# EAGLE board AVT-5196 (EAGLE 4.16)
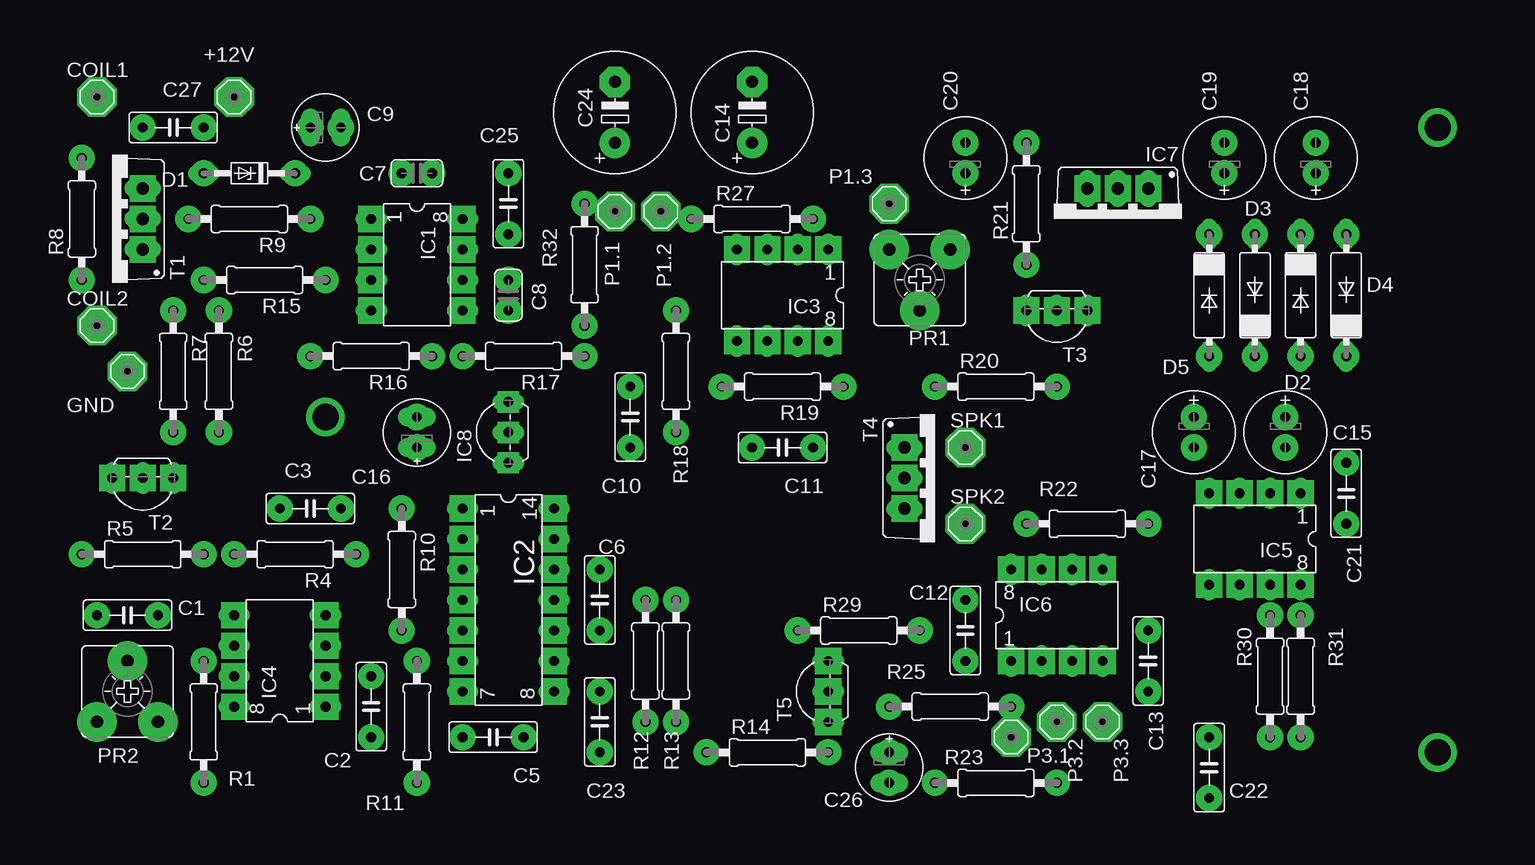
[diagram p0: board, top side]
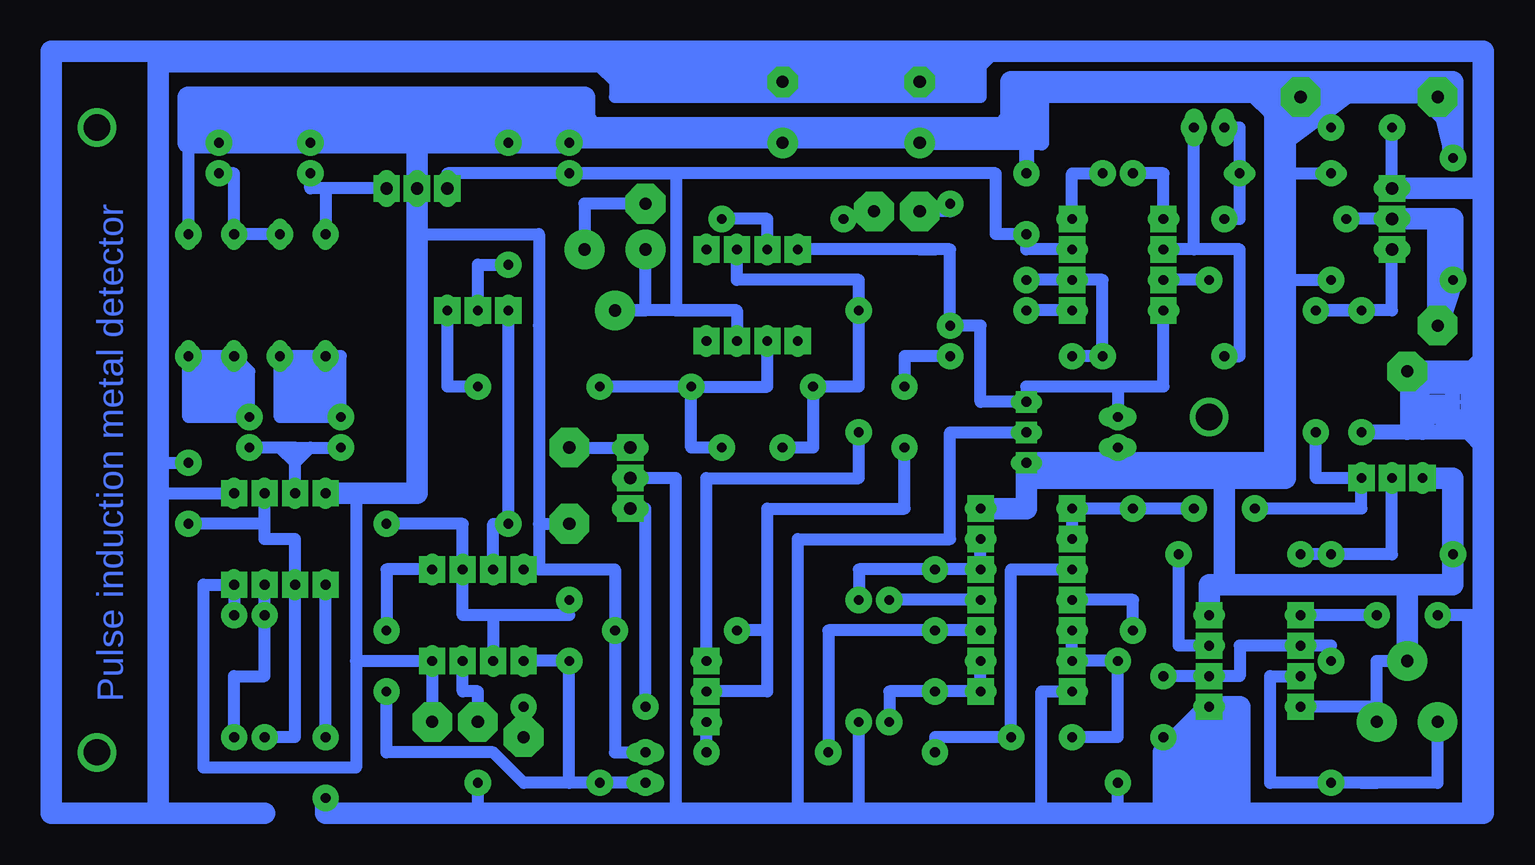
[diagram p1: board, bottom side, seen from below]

No outline drawn. Coordinates in mm, seen from the top.
Copper layers 16: Bottom 0.035mm
Design rules "default": minimum track width 10mil, minimum drill 24mil, track to track 8mil, track to pad 8mil, pad to pad 8mil, via to via 8mil, smd to smd 8mil, copper to edge 40mil, drill to drill 8mil, minimum pad ring 10mil, minimum via ring 8mil, stop-mask expansion 0mil, vias tented up to drill 0mil, thermal gap 10mil

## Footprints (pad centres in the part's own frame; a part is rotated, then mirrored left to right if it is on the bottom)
MCS10B = drill 1.016 pad 2.159 octagon: MP 0,0
C050-025X075 = drill 0.813 octagon: 1 -2.54,0; 2 2.54,0
C025-024X044 = drill 0.813 octagon: 1 -1.27,0; 2 1.27,0
E2,5-6E = drill 0.813 pad 1.575 long: + -1.27,0; - 1.27,0
E5-10,5 = drill 1.016 pad 2.54 round: + -2.54,0 | drill 1.016 pad 2.54 octagon: - 2.54,0
E2,5-7 = drill 0.813 pad 1.6 round: + -1.27,0 | drill 0.813 pad 1.6 octagon: - 1.27,0
DO34Z7 = drill 0.813 long: A 3.81,0; K -3.81,0
DO07 = drill 0.813 long: A 5.08,0; K -5.08,0
DIL08 = drill 0.813 long: 1 -3.81,-3.81; 2 -1.27,-3.81; 3 1.27,-3.81; 4 3.81,-3.81; 5 3.81,3.81; 6 1.27,3.81; 7 -1.27,3.81; 8 -3.81,3.81
DIL14 = drill 0.813 long: 1 -7.62,-3.81; 2 -5.08,-3.81; 3 -2.54,-3.81; 4 0,-3.81; 5 2.54,-3.81; 6 5.08,-3.81; 7 7.62,-3.81; 8 7.62,3.81; 9 5.08,3.81; 10 2.54,3.81; 11 0,3.81; 12 -2.54,3.81; 13 -5.08,3.81; 14 -7.62,3.81
TO220V = drill 1.016 long: 1 -2.54,-2.54; 2 0,-2.54; 3 2.54,-2.54
TO92- = drill 0.813 long: 1 2.54,-1.27; 2 0,-1.27; 3 -2.54,-1.27
CA6V = drill 1.016 long: 1 -2.54,-2.54; 2 0,2.54; 3 2.54,-2.54
0207/10 = drill 0.813 octagon: 1 -5.08,0; 2 5.08,0

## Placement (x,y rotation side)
+12V  [MCS10B]  2.54,80.01 0 top
C1  [C050-025X075]  -6.35,36.83 0 top
C2  [C050-025X075]  13.97,29.21 90 top
C3  [C050-025X075]  8.89,45.72 0 top
C5  [C050-025X075]  24.13,26.67 0 top
C6  [C050-025X075]  33.02,38.1 90 top
C7  [C025-024X044]  17.78,73.66 180 top
C8  [C025-024X044]  25.4,63.5 90 top
C9  [E2,5-6E]  10.16,77.47 0 top
C10  [C050-025X075]  35.56,53.34 90 top
C11  [C050-025X075]  48.26,50.8 180 top
C12  [C050-025X075]  63.5,35.56 270 top
C13  [C050-025X075]  78.74,33.02 270 top
C14  [E5-10,5]  45.72,78.74 90 top
C15  [E2,5-7]  90.17,52.07 270 top
C16  [E2,5-6E]  17.78,52.07 90 top
C17  [E2,5-7]  82.55,52.07 270 top
C18  [E2,5-7]  92.71,74.93 90 top
C19  [E2,5-7]  85.09,74.93 90 top
C20  [E2,5-7]  63.5,74.93 90 top
C21  [C050-025X075]  95.25,46.99 270 top
C22  [C050-025X075]  83.82,24.13 270 top
C23  [C050-025X075]  33.02,27.94 90 top
C24  [E5-10,5]  34.29,78.74 90 top
C25  [C050-025X075]  25.4,71.12 90 top
C26  [E2,5-6E]  57.15,24.13 270 top
C27  [C050-025X075]  -2.54,77.47 0 top
COIL1  [MCS10B]  -8.89,80.01 0 top
COIL2  [MCS10B]  -8.89,60.96 0 top
D1  [DO34Z7]  3.81,73.66 180 top
D2  [DO07]  91.44,63.5 270 top
D3  [DO07]  87.63,63.5 90 top
D4  [DO07]  95.25,63.5 90 top
D5  [DO07]  83.82,63.5 270 top
GND  [MCS10B]  -6.35,57.15 0 top
IC1  [DIL08]  17.78,66.04 270 top
IC2  [DIL14]  25.4,38.1 270 top
IC3  [DIL08]  48.26,63.5 180 top
IC4  [DIL08]  6.35,33.02 90 top
IC5  [DIL08]  87.63,43.18 180 top
IC6  [DIL08]  71.12,36.83 0 top
IC7  [TO220V]  76.2,69.85 180 top
IC8  [TO92-]  24.13,52.07 90 top
P1.1  [MCS10B]  34.29,70.48 0 top
P1.2  [MCS10B]  38.1,70.48 0 top
P1.3  [MCS10B]  57.15,71.12 0 top
P3.1  [MCS10B]  67.31,26.67 0 top
P3.2  [MCS10B]  71.12,27.94 0 top
P3.3  [MCS10B]  74.93,27.94 0 top
PR1  [CA6V]  59.69,64.77 180 top
PR2  [CA6V]  -6.35,30.48 0 top
R1  [0207/10]  0,27.94 90 top
R4  [0207/10]  7.62,41.91 180 top
R5  [0207/10]  -5.08,41.91 0 top
R6  [0207/10]  1.27,57.15 270 top
R7  [0207/10]  -2.54,57.15 270 top
R8  [0207/10]  -10.16,69.85 90 top
R9  [0207/10]  3.81,69.85 180 top
R10  [0207/10]  16.51,40.64 270 top
R11  [0207/10]  17.78,27.94 270 top
R12  [0207/10]  36.83,33.02 270 top
R13  [0207/10]  39.37,33.02 270 top
R14  [0207/10]  46.99,25.4 0 top
R15  [0207/10]  5.08,64.77 180 top
R16  [0207/10]  13.97,58.42 180 top
R17  [0207/10]  26.67,58.42 180 top
R18  [0207/10]  39.37,57.15 90 top
R19  [0207/10]  48.26,55.88 180 top
R20  [0207/10]  66.04,55.88 0 top
R21  [0207/10]  68.58,71.12 90 top
R22  [0207/10]  73.66,44.45 180 top
R23  [0207/10]  66.04,22.86 0 top
R25  [0207/10]  62.23,29.21 180 top
R27  [0207/10]  45.72,69.85 0 top
R29  [0207/10]  54.61,35.56 0 top
R30  [0207/10]  88.9,31.75 90 top
R31  [0207/10]  91.44,31.75 90 top
R32  [0207/10]  31.75,66.04 270 top
SPK1  [MCS10B]  63.5,50.8 0 top
SPK2  [MCS10B]  63.5,44.45 0 top
T1  [TO220V]  -7.62,69.85 90 top
T2  [TO92-]  -5.08,46.99 180 top
T3  [TO92-]  71.12,60.96 180 top
T4  [TO220V]  60.96,48.26 270 top
T5  [TO92-]  50.8,30.48 90 top

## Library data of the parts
+12V COIL1 COIL2 GND P1.1-P1.3 P3.1-P3.3 SPK1 SPK2 = solpad
C1-C3 C5-C27 R1 R4-R23 R25 R27 R29-R32 = rcl
D1-D5 = diode
IC1 IC3-IC6 = dil
IC2 = 40xx
IC7 IC8 T1-T5 = transistor-npn
PR1 PR2 = pot

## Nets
S$1: COIL2.MP R8.1 R9.2 T1.2
S$2: R6.1 R7.1 T1.1
S$3: C19.+ D5.K IC7.1
S$4: C10.2 R17.1
S$5: C3.1 R6.2 T2.3
S$6: R4.2 R5.2 T2.2
S$8: C3.2 IC2.1 IC2.2
S$9: IC4.3 R4.1
S$10: C16.+ C18.- C19.- C20.- C25.2 C26.+ COIL1.MP D1.A D4.A IC2.14 IC4.4 IC4.8 IC5.4 IC5.8 IC6.4 IC6.8 IC7.2 IC8.3 P3.3.MP PR2.2 PR2.3 R5.1 R8.2 R15.2 R21.2 R29.2 R31.2 SPK2.MP T2.1
S$11: C2.2 IC4.2 IC4.6 R1.2
S$12: C1.2 IC4.5
S$13: IC2.4 R10.2
S$14: C5.1 IC2.5 IC2.6 R11.1
S$15: C5.2 C23.1 IC2.3
S$16: C23.2 IC2.8 IC2.9 R12.2
S$17: C6.1 IC2.10 R14.1
S$18: C12.2 C13.2 C26.- IC6.1 R23.1
S$19: IC2.11 R12.1
S$20: C6.2 IC2.12 IC2.13 R13.1
S$21: C11.1 IC3.6 R19.1 R20.1
S$22: C9.+ D1.K R9.1
S$23: C7.2 IC1.1
S$24: C7.1 IC1.8
S$25: R18.1 T5.1
S$26: C8.1 IC1.5
S$27: C22.1 IC5.5
S$28: C9.- IC1.2 R16.2
S$29: IC1.3 R15.1
S$30: IC6.7 R22.2 T3.1
S$31: C8.2 IC1.6 R16.1 R17.2
S$32: C10.1 R29.1 T5.2
S$33: R14.2 T5.3
S$34: C1.1 C2.1 C14.- C21.1 C22.2 C24.- GND.MP IC2.7 IC4.1 IC5.1 IC8.2 R7.2 R11.2 R13.2 R23.2 T1.3 T4.2
S$35: C16.- IC1.4 IC3.4 IC8.1 R32.2
S$36: IC3.3 R27.2
S$37: C11.2 IC3.2 R18.2 R19.2
S$38: P3.1.MP R25.1
S$39: P1.1.MP R32.1
S$40: P1.2.MP R27.1
S$41: P1.3.MP PR1.1
S$42: R20.2 T3.3
S$43: R21.1 T3.2
S$44: C12.1 IC6.2 IC6.6 R22.1
S$47: C21.2 IC5.2 IC5.6 R30.1
S$48: IC5.7 R30.2 R31.1
S$49: C15.- C17.- IC5.3
S$50: C17.+ D3.K D5.A
S$51: C15.+ D2.A D4.K
S$52: D2.K D3.A
S$53: IC4.7 PR2.1 R1.1
S$54: C13.1 IC6.5
S$55: C20.+ C25.1 IC1.7 IC3.7 IC7.3 PR1.2 PR1.3

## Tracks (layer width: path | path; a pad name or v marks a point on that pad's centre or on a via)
S$1  (via drill 0.25 pad 3.3)
  Bottom 1.016: T1.2 R9.2 | COIL2.MP R8.1
  Bottom 1.778: -8.89,69.85 -10.16,69.85 R8.1 COIL2.MP -8.89,69.85 | -8.89,69.85 T1.2
  other vias: -8.89,60.96
S$2
  Bottom 1.016: R7.1 R6.1 -5.08,62.23 T1.1
S$3
  Bottom 1.016: 83.82,72.39 D5.K | IC7.1 83.82,72.39 | 83.82,72.39 85.09,72.39 C19.+
S$4
  Bottom 1.016: R17.1 35.56,58.42 C10.2
S$5
  Bottom 1.016: C3.1 -2.54,45.72 T2.3 1.27,48.26 R6.2
S$6
  Bottom 1.016: T2.2 -5.08,41.91 R5.2 R4.2
S$7  (via drill 0.25 pad 2.18)
  other vias: 78.74,72.39
S$8
  Bottom 1.016: IC2.2 IC2.1 C3.2
S$9
  Bottom 1.016: IC4.3 12.7,34.29 R4.1
S$10  (via drill 0.25 pad 2.18, 0.25 pad 3.3)
  Bottom 1.016: C26.+ 59.69,25.4 R29.2 59.69,40.64 66.04,40.64 | R31.2 IC5.8 93.98,39.37 93.98,24.13 81.28,24.13 | 66.04,40.64 IC6.8 | 66.04,44.45 SPK2.MP | 66.04,44.45 66.04,40.64 | P3.3.MP IC6.4 81.28,33.02 | 81.28,33.02 81.28,24.13 | 66.04,68.58 66.04,60.96 | 66.04,68.58 66.04,44.45 | 95.25,80.01 92.71,80.01 | 85.09,80.01 C19.- | 85.09,80.01 92.71,80.01 | C18.- 92.71,80.01 | 95.25,76.2 D4.A | 76.2,68.58 66.04,68.58 | 81.28,46.99 81.28,33.02 | 81.28,46.99 81.28,24.13 | 81.28,46.99 IC5.4 | 68.58,80.01 R21.2 | 68.58,80.01 63.5,80.01 63.5,78.74 | 81.28,46.99 76.2,46.99 76.2,68.58 | 76.2,68.58 IC7.2 76.2,76.2 76.2,80.01 | 76.2,80.01 85.09,80.01 | 76.2,80.01 68.58,80.01 | 60.96,77.47 62.23,78.74 | 27.94,77.47 26.67,78.74 | C25.2 25.4,76.2 | 25.4,76.2 25.4,77.47 25.4,80.01 | 25.4,76.2 34.29,76.2 C20.- | R8.2 COIL1.MP -1.27,80.01 0,80.01 2.54,80.01 3.81,80.01 5.08,80.01 | 24.13,80.01 6.35,80.01 5.08,80.01 | 5.08,80.01 5.08,78.74 5.08,73.66 | 5.08,73.66 D1.A | 5.08,64.77 5.08,73.66 | 5.08,64.77 R15.2 | 5.08,64.77 5.08,49.53 8.89,49.53 | -6.35,39.37 8.89,39.37 | PR2.2 -3.81,33.02 -3.81,29.21 | -3.81,29.21 IC4.8 | PR2.3 -3.81,29.21 | 17.78,49.53 C16.+
  Bottom 1.27: 24.13,81.28 25.4,81.28 25.4,80.01 | 34.29,76.2 24.13,76.2 24.13,80.01 25.4,80.01 | 25.4,80.01 C25.2 | -10.16,77.47 COIL1.MP R8.2 -10.16,77.47 | -10.16,77.47 -6.35,81.28 -10.16,81.28 -10.16,77.47 | 5.08,78.74 6.35,80.01 | 3.81,76.2 -1.27,80.01 | 2.54,80.01 2.54,78.74 0,80.01 3.81,77.47 2.54,80.01
  Bottom 1.778: 93.98,77.47 64.77,77.47 | 93.98,77.47 93.98,78.74 63.5,78.74 C20.- 76.2,76.2 | IC5.4 76.2,46.99 76.2,76.2 | 93.98,76.2 95.25,76.2 95.25,80.01 62.23,80.01 62.23,78.74 62.23,77.47 60.96,77.47 27.94,77.47 25.4,77.47 | 93.98,76.2 C18.- | 93.98,76.2 93.98,77.47 | 76.2,76.2 93.98,76.2 | 26.67,78.74 26.67,81.28 24.13,81.28 -2.54,81.28 | -2.54,81.28 -6.35,81.28 COIL1.MP | 3.81,80.01 3.81,77.47 3.81,76.2 3.81,53.34 | IC2.14 25.4,45.72 25.4,48.26 | 3.81,53.34 3.81,48.26 25.4,48.26 | T2.1 -10.16,48.26 R5.1 -10.16,39.37 -6.35,39.37 | 25.4,48.26 IC8.3 17.78,49.53 8.89,49.53 | 3.81,53.34 3.81,49.53 8.89,49.53 | 10.16,39.37 IC4.4 | 8.89,49.53 8.89,39.37 10.16,39.37 | -6.35,39.37 10.16,39.37 | PR2.2 -6.35,39.37 | -2.54,81.28 -10.16,81.28 R8.2
  other vias: -8.89,80.01 63.5,44.45 -10.16,74.93
S$11
  Bottom 1.016: R1.2 0,34.29 IC4.6 7.62,34.29 7.62,31.75 IC4.2 C2.2
S$12
  Bottom 1.016: C1.2 IC4.5
S$13
  Bottom 1.016: R10.2 16.51,38.1 IC2.4
S$14
  Bottom 1.016: C5.1 17.78,26.67 R11.1 IC2.6 IC2.5
S$15
  Bottom 1.016: IC2.3 26.67,40.64 C5.2 33.02,26.67 C23.1
S$16
  Bottom 1.016: IC2.9 IC2.8 C23.2 36.83,30.48 R12.2
S$17
  Bottom 1.016: IC2.10 C6.1 41.91,35.56 R14.1
S$18
  Bottom 1.016: IC6.1 C12.2 63.5,22.86 | 63.5,22.86 R23.1 C26.- | C13.2 78.74,25.4 69.85,25.4 67.31,22.86 63.5,22.86
S$19
  Bottom 1.016: IC2.11 R12.1
S$20
  Bottom 1.016: IC2.12 C6.2 39.37,40.64 | IC2.12 IC2.13 IC2.12 | 39.37,40.64 R13.1 | IC2.12 39.37,40.64
S$21
  Bottom 1.016: IC3.6 46.99,55.88 R19.1 | R19.1 53.34,50.8 C11.1 | R19.1 R20.1
S$22
  Bottom 1.016: R9.1 7.62,69.85 D1.K 7.62,77.47 C9.+
S$23
  Bottom 1.016: IC1.1 13.97,73.66 C7.2
S$24
  Bottom 1.016: IC1.8 21.59,73.66 C7.1
S$25
  Bottom 1.016: R18.1 39.37,48.26 52.07,48.26 T5.1
S$26
  Bottom 1.016: IC1.5 C8.1
S$27
  Bottom 1.016: C22.1 IC5.5
S$28
  Bottom 1.016: 11.43,67.31 7.62,67.31 7.62,58.42 R16.2 | 11.43,67.31 C9.- | 11.43,67.31 IC1.2
S$29
  Bottom 1.016: R15.1 IC1.3
S$30
  Bottom 1.016: T3.1 R22.2 69.85,44.45 IC6.7
S$31
  Bottom 1.016: C8.2 IC1.6 19.05,64.77 R16.1 R17.2
S$32
  Bottom 1.016: C10.1 35.56,45.72 46.99,45.72 46.99,35.56 | 46.99,35.56 R29.1 | 46.99,35.56 46.99,30.48 T5.2
S$33
  Bottom 1.016: R14.2 T5.3
S$34  (via drill 0.25 pad 2.18)
  Bottom 1.016: 97.79,46.99 IC5.1 | 97.79,49.53 C21.1 | 97.79,49.53 97.79,46.99 | IC8.2 31.75,52.07 31.75,43.18 44.45,43.18 44.45,20.32 | 97.79,38.1 97.79,46.99 | 97.79,49.53 97.79,82.55 60.96,82.55 | 46.99,83.82 45.72,83.82 | 45.72,83.82 C14.- | T4.2 54.61,48.26 54.61,20.32 | 71.12,20.32 R23.2 | 71.12,20.32 83.82,20.32 | 54.61,20.32 71.12,20.32 | 44.45,20.32 54.61,20.32 | 34.29,83.82 45.72,83.82 | 34.29,83.82 34.29,82.55 | 34.29,83.82 C24.- | 34.29,83.82 27.94,83.82 29.21,82.55 | T1.3 -5.08,77.47 | IC2.7 24.13,30.48 24.13,20.32 | 39.37,20.32 44.45,20.32 | 39.37,20.32 54.61,20.32 | 39.37,20.32 R13.2 | IC4.1 10.16,26.67 12.7,26.67 C2.1 13.97,25.4 | 24.13,20.32 39.37,20.32 | -6.35,52.07 R7.2 | 17.78,20.32 24.13,20.32 | 17.78,20.32 R11.2 | 13.97,20.32 17.78,20.32 | -12.7,36.83 -12.7,50.8 | -12.7,36.83 -11.43,36.83 | -11.43,36.83 C1.1 | -12.7,20.32 -12.7,36.83 | -11.43,20.32 -11.43,36.83 | 29.21,82.55 29.21,81.28 | 29.21,81.28 29.21,80.01 59.69,80.01 59.69,81.28 | 59.69,83.82 59.69,82.55 | 29.21,82.55 30.48,82.55 | 29.21,82.55 30.48,81.28 | 30.48,81.28 31.75,81.28 | 31.75,81.28 39.37,81.28 | 41.91,81.28 39.37,81.28 | 58.42,81.28 41.91,81.28 | 59.69,82.55 58.42,82.55 | 58.42,82.55 53.34,82.55 | 33.02,82.55 38.1,82.55 | 31.75,82.55 33.02,82.55 | 30.48,82.55 31.75,82.55 | 30.48,82.55 30.48,81.28 | 30.48,81.28 31.75,82.55 | 31.75,81.28 31.75,82.55 | 31.75,81.28 33.02,82.55 | 33.02,82.55 39.37,81.28 | 58.42,82.55 39.37,81.28 | 58.42,81.28 53.34,82.55 | 53.34,82.55 38.1,82.55 | 41.91,81.28 38.1,82.55 | 58.42,82.55 41.91,81.28 | 58.42,81.28 58.42,82.55 | 59.69,82.55 59.69,81.28 | 58.42,81.28 59.69,82.55 | 58.42,81.28 59.69,81.28 | 29.21,81.28 58.42,81.28 | 59.69,82.55 60.96,82.55 | 59.69,81.28 60.96,82.55
  Bottom 1.27: GND.MP -6.35,52.07 -7.62,52.07 | -12.7,52.07 -11.43,52.07 | -11.43,52.07 -7.62,52.07 | -7.62,52.07 R7.2 | -7.62,52.07 -7.62,54.61 | -7.62,54.61 -7.62,55.88 -10.16,55.88 | -10.16,55.88 -11.43,55.88 -11.43,53.34 | -11.43,53.34 -10.16,53.34 | -10.16,53.34 -8.89,53.34 -7.62,54.61 | -7.62,54.61 -8.89,54.61 | -8.89,54.61 -10.16,54.61 | -10.16,53.34 -10.16,55.88 | -7.62,52.07 -8.89,54.61 | -11.43,53.34 -12.7,50.8 -11.43,52.07 | -11.43,53.34 -11.43,52.07 | -12.7,58.42 -10.16,55.88
  Bottom 1.778: -12.7,57.15 GND.MP | -12.7,57.15 -12.7,58.42 -12.7,72.39 | -12.7,72.39 -12.7,83.82 27.94,83.82 50.8,83.82 | -12.7,72.39 T1.3 | 50.8,83.82 59.69,83.82 97.79,83.82 | 50.8,83.82 46.99,83.82 | 97.79,83.82 97.79,82.55 97.79,38.1 97.79,20.32 | 97.79,20.32 96.52,20.32 | 7.62,20.32 13.97,20.32 | 7.62,20.32 -11.43,20.32 -12.7,20.32 -12.7,50.8 -12.7,52.07 -12.7,57.15 | IC4.1 7.62,29.21 7.62,20.32 | 7.62,20.32 11.43,20.32 12.7,21.59 12.7,25.4 8.89,25.4 | 8.89,25.4 8.89,27.94 | 8.89,25.4 8.89,21.59 11.43,21.59 11.43,24.13 10.16,24.13 | 10.16,24.13 10.16,22.86 | IC4.1 10.16,24.13 | IC4.1 12.7,26.67 13.97,25.4 13.97,20.32 | 97.79,20.32 106.68,20.32 106.68,83.82 97.79,83.82 | 97.79,20.32 88.9,20.32 | C22.2 83.82,20.32 13.97,20.32
  other vias: 83.82,21.59
S$35
  Bottom 1.016: 17.78,55.88 C16.- | 17.78,55.88 25.4,55.88 IC8.1 29.21,54.61 29.21,60.96 R32.2 31.75,67.31 34.29,67.31 | IC1.4 13.97,55.88 17.78,55.88 | 34.29,67.31 33.02,67.31 | 34.29,67.31 IC3.4
S$36
  Bottom 1.016: IC3.3 46.99,69.85 R27.2
S$37
  Bottom 1.016: C11.2 43.18,50.8 R19.2 39.37,55.88 R18.2 39.37,64.77 49.53,64.77 IC3.2
S$38
  Bottom 1.016: P3.1.MP R25.1
S$39
  Bottom 1.016: R32.1 31.75,70.48 P1.1.MP
S$40
  Bottom 1.016: P1.2.MP R27.1
S$41
  Bottom 1.016: P1.3.MP 62.23,71.12 PR1.1
S$42
  Bottom 1.016: R20.2 73.66,55.88 T3.3
S$43
  Bottom 1.016: T3.2 71.12,66.04 R21.1
S$44
  Bottom 1.016: 69.85,36.83 72.39,36.83 IC6.6 72.39,44.45 R22.1 | 69.85,36.83 IC6.2 | C12.1 63.5,36.83 69.85,36.83
S$45  (via drill 0.25 pad 2.18)
  other vias: 8.89,58.42
S$47
  Bottom 1.016: 88.9,44.45 88.9,43.18 86.36,43.18 IC5.6 86.36,26.67 R30.1 | 88.9,44.45 IC5.2 | 88.9,44.45 C21.2
S$48
  Bottom 1.016: IC5.7 R30.2 88.9,31.75 91.44,31.75 R31.1
S$49
  Bottom 1.016: 86.36,50.8 87.63,50.8 | 87.63,50.8 C15.- | 85.09,50.8 C17.- | 86.36,50.8 85.09,50.8 | 86.36,49.53 86.36,50.8 | IC5.3 86.36,49.53 | 86.36,49.53 85.09,50.8 | 86.36,49.53 87.63,50.8
S$50
  Bottom 1.016: D5.A D3.K 87.63,53.34 C17.+ D5.A
S$51
  Bottom 1.016: D2.A D4.K 95.25,53.34 C15.+ | C15.+ 90.17,57.15 D2.A | C15.+ D2.A
S$52  (via drill 0.25 pad 2.18)
  Bottom 1.016: D3.A D2.K 91.44,73.66 v92.71,73.66
S$53
  Bottom 1.016: IC4.7 5.08,31.75 5.08,22.86 R1.1 -2.54,22.86 | -2.54,22.86 -3.81,22.86 | -2.54,22.86 -8.89,22.86 PR2.1
S$54
  Bottom 1.016: IC6.5 78.74,40.64 C13.1
S$55
  Bottom 1.016: PR1.3 57.15,62.23 PR1.2 49.53,62.23 | 49.53,62.23 IC3.7 | IC7.3 73.66,73.66 C20.+ | 49.53,62.23 54.61,62.23 54.61,73.66 C20.+ | C20.+ 27.94,73.66 27.94,68.58 C25.1 25.4,67.31 IC1.7
S$56  (via drill 0.61)
  other vias: 10.16,53.34
S$57  (via drill 0.61)
  other vias: 102.87,77.47
S$58  (via drill 0.25 pad 3.3)
  other vias: 57.15,71.12
S$59  (via drill 2.18)
  other vias: 102.87,77.47
S$60  (via drill 0.25 pad 1.42)
  other vias: 102.87,77.47
S$61  (via drill 0.25 pad 2.18)
  other vias: 92.71,76.2
S$62  (via drill 0.25 pad 1.42)
  other vias: 102.87,25.4
S$63  (via drill 0.25 pad 2.18)
  other vias: 85.09,76.2
S$64  (via drill 0.25 pad 2.18)
  other vias: 85.09,73.66
S$65  (via drill 0.25 pad 1.42)
  other vias: 10.16,53.34
S$66  (via drill 0.25 pad 2.18)
  other vias: 95.25,68.58
S$67  (via drill 0.25 pad 3.3)
  other vias: -3.81,27.94
S$68  (via drill 0.25 pad 3.3)
  other vias: 62.23,67.31
S$69  (via drill 0.25 pad 2.18)
  other vias: 21.59,64.77
S$70  (via drill 0.25 pad 1.78)
  other vias: 91.44,46.99
S$71  (via drill 0.25 pad 3.3)
  other vias: 74.93,27.94
S$72  (via drill 0.25 pad 3.3)
  other vias: -6.35,57.15
S$73  (via drill 0.25 pad 2.18)
  other vias: 67.31,29.21
S$74  (via drill 0.25 pad 3.3)
  other vias: 2.54,80.01
S$75  (via drill 0.25 pad 2.18, 0.25 pad 3.3)
  Bottom 1.016: v63.5,50.8 v58.42,50.8
  other vias: 52.07,59.69 49.53,59.69 46.99,59.69 44.45,59.69 52.07,67.31 49.53,67.31 46.99,67.31 44.45,67.31
S$76  (via drill 0.25 pad 3.3)
  other vias: 38.1,70.48
S$77  (via drill 0.25 pad 2.18)
  other vias: -10.16,64.77
S$78  (via drill 0.25 pad 2.18)
  other vias: 1.27,52.07
S$79  (via drill 0.25 pad 2.18)
  other vias: -2.54,52.07
S$80  (via drill 0.25 pad 2.18)
  other vias: 0,64.77
S$81  (via drill 0.25 pad 2.18)
  other vias: -5.08,69.85
S$82  (via drill 0.25 pad 2.18)
  other vias: -1.27,69.85
S$83  (via drill 0.25 pad 2.18)
  other vias: 0,77.47
S$84  (via drill 0.25 pad 2.18)
  other vias: -5.08,77.47
S$86  (via drill 0.25 pad 2.18)
  other vias: 0,73.66
S$87  (via drill 0.25 pad 2.18)
  other vias: 8.89,69.85
S$88  (via drill 0.25 pad 2.18)
  other vias: 7.62,73.66
S$89  (via drill 0.25 pad 2.18)
  other vias: 11.43,77.47
S$90  (via drill 0.25 pad 2.18)
  other vias: 8.89,77.47
S$91  (via drill 0.25 pad 2.18)
  other vias: 19.05,73.66
S$92  (via drill 0.25 pad 2.18)
  other vias: 45.72,81.28
S$93  (via drill 0.25 pad 2.18)
  other vias: 25.4,68.58
S$94  (via drill 0.25 pad 2.18)
  other vias: 25.4,73.66
S$95  (via drill 0.25 pad 2.18)
  other vias: 31.75,71.12
S$96  (via drill 0.25 pad 2.18)
  other vias: 34.29,76.2
S$97  (via drill 0.25 pad 2.18)
  other vias: 45.72,76.2
S$98  (via drill 0.25 pad 2.18)
  other vias: 34.29,81.28
S$99  (via drill 2.18)
  other vias: 10.16,53.34
S$100  (via drill 0.25 pad 2.18)
  other vias: 40.64,69.85
S$101  (via drill 0.25 pad 2.18)
  other vias: -10.16,41.91
S$102  (via drill 0.25 pad 2.18)
  other vias: 25.4,64.77
S$103  (via drill 0.25 pad 2.18)
  other vias: 102.87,77.47
S$104  (via drill 0.25 pad 2.18)
  other vias: 39.37,52.07
S$105  (via drill 0.25 pad 2.18)
  other vias: 35.56,50.8
S$106  (via drill 0.25 pad 2.18)
  other vias: 35.56,55.88
S$107  (via drill 0.25 pad 2.18)
  other vias: 43.18,55.88
S$108  (via drill 0.25 pad 2.18)
  other vias: 45.72,50.8
S$109  (via drill 0.25 pad 2.18)
  other vias: 102.87,25.4
S$110  (via drill 0.25 pad 2.18)
  other vias: 10.16,64.77
S$111  (via drill 0.25 pad 2.18)
  other vias: 21.59,58.42
S$112  (via drill 0.25 pad 2.18)
  other vias: 17.78,53.34
S$113  (via drill 0.25 pad 2.18)
  other vias: 12.7,41.91
S$114  (via drill 0.25 pad 2.18)
  other vias: 16.51,45.72
S$115  (via drill 0.25 pad 1.78)
  other vias: -5.08,48.26
S$116  (via drill 0.25 pad 1.78)
  other vias: -2.54,48.26
S$117  (via drill 0.25 pad 1.78)
  other vias: -7.62,48.26
S$118  (via drill 0.25 pad 2.18)
  other vias: 6.35,45.72
S$119  (via drill 0.25 pad 2.18)
  other vias: 11.43,45.72
S$120  (via drill 0.25 pad 1.78)
  other vias: 10.16,31.75
S$121  (via drill 0.25 pad 1.78)
  other vias: 25.4,52.07
S$122  (via drill 0.25 pad 1.78)
  other vias: 29.21,45.72
S$123  (via drill 0.25 pad 1.78)
  other vias: 21.59,45.72
S$124  (via drill 0.25 pad 1.78)
  other vias: 21.59,43.18
S$125  (via drill 0.25 pad 1.78)
  other vias: 21.59,40.64
S$126  (via drill 0.25 pad 1.78)
  other vias: 21.59,33.02
S$127  (via drill 0.25 pad 1.78)
  other vias: 2.54,31.75
S$128  (via drill 0.25 pad 2.18)
  other vias: 2.54,41.91
S$129  (via drill 0.25 pad 2.18)
  other vias: 0,33.02
S$130  (via drill 0.25 pad 2.18)
  other vias: -3.81,36.83
S$131  (via drill 0.25 pad 2.18)
  other vias: 0,41.91
S$132  (via drill 0.25 pad 1.78)
  other vias: 2.54,36.83
S$133  (via drill 0.25 pad 1.78)
  other vias: 2.54,34.29
S$134  (via drill 0.25 pad 1.78)
  other vias: 2.54,29.21
S$135  (via drill 0.25 pad 2.18)
  other vias: 0,22.86
S$136  (via drill 0.25 pad 3.3)
  other vias: -6.35,33.02
S$137  (via drill 0.25 pad 3.3)
  other vias: -8.89,27.94
S$138  (via drill 0.25 pad 2.18)
  other vias: 16.51,35.56
S$139  (via drill 0.25 pad 2.18)
  other vias: 13.97,31.75
S$140  (via drill 0.25 pad 2.18)
  other vias: 13.97,26.67
S$141  (via drill 0.25 pad 2.18)
  other vias: 17.78,22.86
S$142  (via drill 0.25 pad 2.18)
  other vias: 21.59,26.67
S$143  (via drill 0.25 pad 2.18)
  other vias: 26.67,26.67
S$144  (via drill 0.25 pad 2.18)
  other vias: 33.02,25.4
S$145  (via drill 0.25 pad 1.78)
  other vias: 29.21,33.02
S$146  (via drill 0.25 pad 2.18)
  other vias: 39.37,38.1
S$147  (via drill 0.25 pad 2.18)
  other vias: 33.02,35.56
S$148  (via drill 0.25 pad 2.18)
  other vias: 33.02,40.64
S$149  (via drill 0.25 pad 2.18)
  other vias: 33.02,30.48
S$150  (via drill 0.25 pad 2.18)
  other vias: 36.83,27.94
S$151  (via drill 0.25 pad 2.18)
  other vias: 39.37,27.94
S$152  (via drill 0.25 pad 2.18)
  other vias: 41.91,25.4
S$153  (via drill 0.25 pad 2.18)
  other vias: 49.53,35.56
S$154  (via drill 0.25 pad 1.78)
  other vias: 52.07,33.02
S$155  (via drill 0.25 pad 2.18)
  other vias: 52.07,25.4
S$156  (via drill 0.25 pad 1.78)
  other vias: 52.07,27.94
S$157  (via drill 0.25 pad 1.78)
  other vias: 52.07,30.48
S$158  (via drill 0.25 pad 2.18)
  other vias: 71.12,22.86
S$159  (via drill 0.25 pad 2.18)
  other vias: 63.5,76.2
S$160  (via drill 0.25 pad 1.78)
  other vias: 10.16,36.83
S$161  (via drill 0.25 pad 1.78)
  other vias: 10.16,34.29
S$162  (via drill 0.25 pad 1.78)
  other vias: 10.16,29.21
S$163  (via drill 0.25 pad 2.18)
  other vias: 17.78,33.02
S$164  (via drill 0.25 pad 1.78)
  other vias: 21.59,38.1
S$165  (via drill 0.25 pad 1.78)
  other vias: 21.59,35.56
S$166  (via drill 0.25 pad 1.78)
  other vias: 21.59,30.48
S$167  (via drill 0.25 pad 1.78)
  other vias: 29.21,43.18
S$168  (via drill 0.25 pad 1.78)
  other vias: 29.21,40.64
S$169  (via drill 0.25 pad 1.78)
  other vias: 29.21,38.1
S$170  (via drill 0.25 pad 1.78)
  other vias: 29.21,35.56
S$171  (via drill 0.25 pad 1.78)
  other vias: 29.21,30.48
S$172  (via drill 0.25 pad 1.78)
  other vias: 25.4,54.61
S$173  (via drill 0.25 pad 1.78)
  other vias: 25.4,49.53
S$174  (via drill 0.25 pad 2.18)
  other vias: 17.78,50.8
S$175  (via drill 0.25 pad 2.18)
  other vias: 19.05,58.42
S$176  (via drill 0.25 pad 2.18)
  other vias: 31.75,58.42
S$177  (via drill 0.25 pad 1.78)
  other vias: 44.45,59.69
S$178  (via drill 0.25 pad 1.78)
  other vias: 46.99,59.69
S$179  (via drill 0.25 pad 1.78)
  other vias: 49.53,59.69
S$180  (via drill 0.25 pad 1.78)
  other vias: 52.07,67.31
S$181  (via drill 0.25 pad 1.78)
  other vias: 52.07,59.69
S$182  (via drill 0.25 pad 2.18)
  other vias: 50.8,50.8
S$183  (via drill 0.25 pad 2.18)
  other vias: 53.34,55.88
S$184  (via drill 0.25 pad 2.18)
  other vias: 36.83,38.1
S$185  (via drill 0.25 pad 2.18)
  other vias: 59.69,35.56
S$186  (via drill 0.25 pad 2.18)
  other vias: 63.5,33.02
S$187  (via drill 0.25 pad 2.18)
  other vias: 63.5,38.1
S$188  (via drill 0.25 pad 2.18)
  Bottom 1.016: v58.42,45.72 57.15,45.72 v57.15,29.21
S$189  (via drill 0.25 pad 2.18)
  other vias: 58.42,48.26
S$191  (via drill 0.25 pad 2.18)
  other vias: 102.87,77.47
S$192  (via drill 0.25 pad 1.78)
  other vias: 73.66,62.23
S$193  (via drill 0.25 pad 2.18)
  other vias: 57.15,25.4
S$194  (via drill 0.25 pad 2.18)
  other vias: 68.58,44.45
S$195  (via drill 0.25 pad 1.78)
  other vias: 69.85,40.64
S$196  (via drill 0.25 pad 1.78)
  other vias: 67.31,40.64
S$197  (via drill 0.25 pad 1.78)
  other vias: 72.39,40.64 72.39,40.64
S$198  (via drill 0.25 pad 1.78)
  other vias: 69.85,33.02
S$199  (via drill 0.25 pad 1.78)
  other vias: 74.93,40.64 72.39,40.64
S$200  (via drill 0.25 pad 2.18)
  other vias: 91.44,36.83
S$201  (via drill 0.25 pad 2.18)
  other vias: 78.74,35.56
S$202  (via drill 0.25 pad 1.78)
  other vias: 74.93,33.02
S$203  (via drill 0.25 pad 1.78, 0.25 pad 3.3)
  Bottom 1.016: v71.12,27.94 71.12,30.48 72.39,30.48 v72.39,33.02
S$204  (via drill 0.25 pad 1.78)
  other vias: 67.31,33.02
S$205  (via drill 0.25 pad 3.3)
  other vias: 67.31,26.67
S$206  (via drill 0.25 pad 2.18)
  other vias: 10.16,53.34
S$207  (via drill 0.25 pad 2.18)
  other vias: 78.74,30.48
S$208  (via drill 0.25 pad 2.18)
  other vias: 60.96,22.86
S$210  (via drill 0.25 pad 2.18)
  other vias: 83.82,26.67
S$211  (via drill 0.25 pad 2.18)
  other vias: 88.9,26.67
S$212  (via drill 0.25 pad 2.18)
  other vias: 91.44,26.67
S$213  (via drill 0.25 pad 2.18)
  other vias: 88.9,36.83
S$214  (via drill 0.25 pad 1.78)
  other vias: 86.36,39.37
S$215  (via drill 0.25 pad 1.78)
  other vias: 88.9,39.37
S$216  (via drill 0.25 pad 1.78)
  other vias: 83.82,39.37
S$217  (via drill 0.25 pad 1.78)
  other vias: 91.44,39.37
S$218  (via drill 0.25 pad 2.18)
  other vias: 78.74,44.45
S$219  (via drill 0.25 pad 2.18)
  other vias: 95.25,44.45
S$220  (via drill 0.25 pad 1.78)
  other vias: 86.36,46.99
S$221  (via drill 0.25 pad 1.78)
  other vias: 88.9,46.99
S$222  (via drill 0.25 pad 1.78)
  other vias: 83.82,46.99
S$223  (via drill 0.25 pad 2.18)
  other vias: 95.25,49.53
S$224  (via drill 0.25 pad 2.18)
  other vias: 90.17,50.8
S$225  (via drill 0.25 pad 2.18)
  other vias: 90.17,53.34
S$226  (via drill 0.25 pad 2.18)
  Bottom 1.016: v83.82,58.42 82.55,58.42 v82.55,53.34
S$227  (via drill 0.25 pad 2.18)
  other vias: 87.63,58.42
S$228  (via drill 0.25 pad 2.18)
  other vias: 91.44,58.42
S$229  (via drill 0.25 pad 2.18)
  other vias: 95.25,58.42
S$230  (via drill 0.25 pad 2.18)
  other vias: 71.12,55.88
S$231  (via drill 0.25 pad 1.78)
  other vias: 68.58,62.23
S$232  (via drill 0.25 pad 1.78)
  other vias: 71.12,62.23
S$233  (via drill 0.25 pad 2.18)
  other vias: 68.58,66.04
S$234  (via drill 0.25 pad 2.18)
  other vias: 83.82,68.58
S$235  (via drill 0.25 pad 2.18)
  other vias: 87.63,68.58
S$236  (via drill 0.25 pad 2.18)
  other vias: 91.44,68.58
S$237  (via drill 0.25 pad 3.3)
  other vias: 59.69,62.23
S$238  (via drill 0.25 pad 3.3)
  other vias: 57.15,67.31
S$239  (via drill 0.25 pad 2.18)
  other vias: 50.8,69.85
S$240  (via drill 0.25 pad 2.18)
  other vias: 39.37,62.23
S$241  (via drill 0.25 pad 1.78)
  other vias: 44.45,67.31
S$242  (via drill 0.25 pad 1.78)
  other vias: 46.99,67.31
S$243  (via drill 0.25 pad 1.78)
  other vias: 49.53,67.31
S$244  (via drill 0.25 pad 2.18)
  other vias: 73.66,72.39 68.58,62.23 71.12,62.23 73.66,62.23
S$245  (via drill 0.25 pad 2.18)
  other vias: 76.2,72.39
S$246  (via drill 0.25 pad 2.18)
  other vias: 68.58,76.2
S$247  (via drill 0.25 pad 2.18)
  other vias: 63.5,73.66
S$248  (via drill 2.18)
  other vias: 102.87,77.47
S$249  (via drill 0.25 pad 2.18)
  other vias: 82.55,50.8
S$250  (via drill 0.25 pad 2.18)
  other vias: -2.54,62.23
S$251  (via drill 0.25 pad 2.18)
  other vias: 1.27,62.23
S$252  (via drill 0.25 pad 2.18)
  other vias: -8.89,36.83
S$253  (via drill 0.25 pad 2.18)
  other vias: 13.97,64.77
S$254  (via drill 0.25 pad 2.18)
  other vias: 13.97,69.85
S$255  (via drill 0.25 pad 2.18)
  other vias: 13.97,67.31
S$256  (via drill 0.25 pad 2.18)
  other vias: 13.97,62.23 10.16,36.83 10.16,34.29 10.16,31.75 10.16,29.21 2.54,29.21 2.54,31.75 2.54,34.29 2.54,36.83 52.07,33.02 52.07,30.48 52.07,27.94 29.21,45.72 29.21,43.18 29.21,40.64 29.21,38.1 29.21,35.56 29.21,33.02 29.21,30.48 21.59,30.48 21.59,33.02 21.59,35.56 21.59,38.1 21.59,40.64 21.59,43.18 21.59,45.72 67.31,33.02 69.85,33.02 72.39,33.02 74.93,33.02 74.93,40.64 72.39,40.64 69.85,40.64 67.31,40.64 83.82,46.99 86.36,46.99 88.9,46.99 91.44,46.99 83.82,39.37 86.36,39.37 88.9,39.37 91.44,39.37 -2.54,48.26 -5.08,48.26 -7.62,48.26
S$257  (via drill 0.25 pad 2.18)
  other vias: 21.59,69.85
S$258  (via drill 0.25 pad 2.18)
  other vias: 21.59,67.31
S$259  (via drill 0.25 pad 2.18)
  other vias: 21.59,62.23
S$260  (via drill 0.25 pad 2.18)
  other vias: 25.4,62.23
S$261  (via drill 0.25 pad 2.18)
  other vias: -5.08,72.39
S$262  (via drill 0.25 pad 2.18)
  other vias: -5.08,67.31
S$263  (via drill 0.25 pad 2.18)
  other vias: 16.51,73.66
S$264  (via drill 0.25 pad 2.18)
  other vias: 102.87,25.4
S$265  (via drill 0.25 pad 2.18)
  other vias: 102.87,25.4
S$266  (via drill 2.18)
  other vias: 102.87,25.4
S$267  (via drill 0.25 pad 2.18)
  other vias: 31.75,60.96
S$268  (via drill 0.25 pad 2.18)
  other vias: 60.96,55.88
S$269  (via drill 0.25 pad 3.3)
  other vias: 34.29,70.48
S$270  (via drill 0.25 pad 2.18)
  other vias: 57.15,22.86
(copper drawn outside any net)
  shapes: Bottom area x6

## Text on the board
Bottom: Pulse induction metal detector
